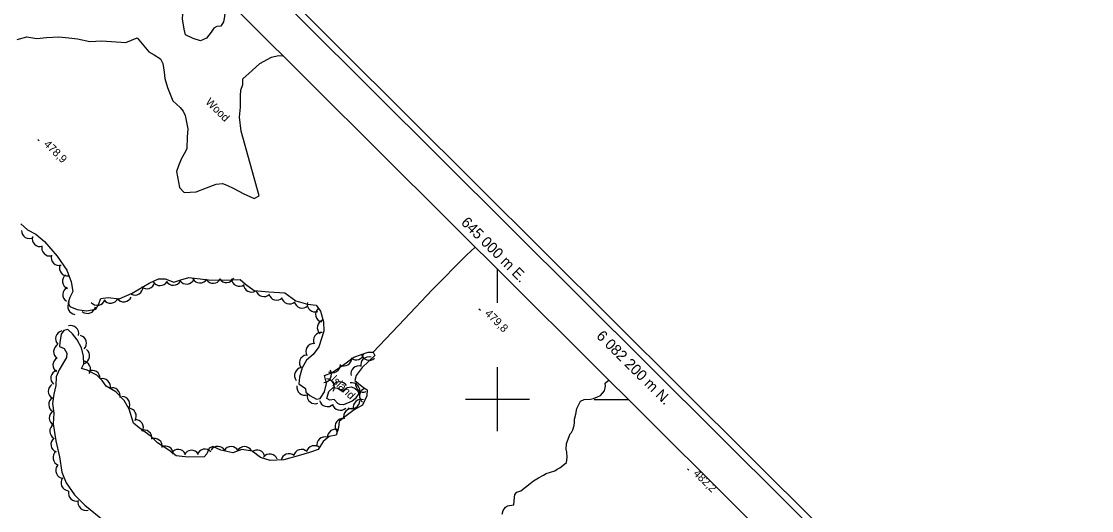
# Model space of a CAD drawing. Extents: x 642515 to 647219, y 6080136 to 6084356.
# Drawn here: x 644821.8 to 645222.7, y 6082158.4 to 6082341.5 of the extents above; entities that cross this region are included whole.
import ezdxf

# ---------------------------------------------------------------- set-up
doc = ezdxf.new("R2010")
doc.units = 0
for name, color, linetype in [('Level 1', 7, 'Continuous'), ('Level 2', 7, 'Continuous'), ('Level 3', 7, 'Continuous'), ('Level 4', 7, 'Continuous'), ('Level 44', 7, 'Continuous'), ('Level 60', 7, 'Continuous'), ('Level 61', 7, 'Continuous'), ('Level 8', 7, 'Continuous')]:
    doc.layers.add(name, color=color, linetype=linetype)

msp = doc.modelspace()

# ---------------------------------------------------------------- linework, layer by layer
at = {"layer": 'Level 1'}
for points in [[(644820.13, 6082334.71), (644823.82, 6082335.72), (644827.59, 6082335.11), (644831.11, 6082335.43), (644835.81, 6082335.68), (644839.57, 6082335.31), (644842.79, 6082335.04), (644847.43, 6082334.03), (644851.89, 6082334.27), (644860.86, 6082333.61), (644865.17, 6082335.31), (644869.48, 6082330.17), (644871.49, 6082328.98), (644873.84, 6082327.48)], [(644873.84, 6082327.48), (644874.73, 6082325.73), (644875.21, 6082322.51), (644875.49, 6082320.08), (644876.46, 6082316.71), (644878.48, 6082311.78), (644881.2, 6082309.32), (644882.4, 6082307.92), (644883.13, 6082306.33), (644884.18, 6082301.35), (644883.84, 6082298.24), (644883.71, 6082294), (644883.28, 6082292.84), (644881.63, 6082289.98), (644880.61, 6082287.49), (644879.9, 6082285.34), (644881, 6082279.38), (644882.71, 6082277.52), (644887.25, 6082277.76), (644891.07, 6082279.27), (644894.75, 6082280.61), (644897.17, 6082280.9), (644898.67, 6082280.17), (644901.32, 6082279.01), (644904.83, 6082277.09), (644908.98, 6082275.2), (644910.88, 6082276.28), (644904.05, 6082300.47), (644903.48, 6082305.64), (644903.79, 6082309.4), (644903.91, 6082313.64), (644903.97, 6082315.76), (644904.68, 6082317.91), (644904.75, 6082320.03), (644908.18, 6082323.15), (644911.14, 6082325.75), (644915.42, 6082328.09), (644918.15, 6082328.73), (644919.73, 6082328.64)], [(645018.38, 6082172.27), (645021.58, 6082173.26), (645022.52, 6082173.96), (645023.55, 6082174.42), (645024.65, 6082175.29), (645025.98, 6082176.42), (645026.3, 6082178.3), (645026.12, 6082180.32), (645025.91, 6082181.45), (645025.97, 6082183.56), (645027.35, 6082187.12), (645027.89, 6082187.72), (645028.42, 6082188.64), (645028.83, 6082190.29), (645028.94, 6082191.43), (645028.96, 6082192.65), (645029.44, 6082194.54), (645029.83, 6082196.67), (645031.24, 6082199.43), (645032.59, 6082200.07), (645034.95, 6082200.12), (645036.15, 6082200.43), (645037.58, 6082200.99), (645038.7, 6082201.54), (645040.24, 6082203.25), (645040.57, 6082204.97), (645040.51, 6082206.1), (645041.45, 6082206.96), (645041.94, 6082207.18)], [(645001.88, 6082157.1), (645002.22, 6082158.5), (645003.14, 6082159.69), (645003.93, 6082160.21), (645006.26, 6082160.58), (645006.54, 6082163.28), (645006.65, 6082164.42), (645007.43, 6082165.27), (645008.86, 6082165.84), (645012.39, 6082168.54), (645013.64, 6082169.58), (645015.53, 6082170.66), (645017.35, 6082171.65), (645018.38, 6082172.27)]]:
    msp.add_lwpolyline(points, dxfattribs=at)
at = {"layer": 'Level 2'}
msp.add_lwpolyline([(644897.23, 6082351), (644897.49, 6082348.13), (644898.11, 6082345.4), (644897.76, 6082342.62), (644897.49, 6082341.3), (644896.43, 6082339.78), (644894.98, 6082339.54), (644893.87, 6082338.99), (644892.8, 6082337.47), (644891.12, 6082335.27), (644888.9, 6082334.17), (644886.1, 6082335.16), (644883.28, 6082336.47), (644882.69, 6082338.55), (644882.18, 6082342.43), (644882.26, 6082344.22), (644878.57, 6082346.62)], dxfattribs=at)
at = {"layer": 'Level 3'}
for p, q in [((644827.89, 6082297.32), (644828.46, 6082296.76)), ((644993.17, 6082233.97), (644993.74, 6082233.41)), ((645071.29, 6082174.1), (645071.86, 6082173.54))]:
    msp.add_line(p, q, dxfattribs=at)
at = {"layer": 'Level 4'}
for points in [[(644821.58, 6082265.8), (644824.08, 6082263.54), (644827.12, 6082261.89), (644830.39, 6082259.1), (644835.11, 6082253.59), (644838.75, 6082248.43), (644840.46, 6082244.08), (644841.06, 6082240.41), (644839.95, 6082238.12), (644839.31, 6082236.36), (644839.96, 6082234.83), (644842.65, 6082233.66), (644846.12, 6082233.19), (644849.62, 6082233.78), (644850.59, 6082235.56), (644851.54, 6082237.84), (644854.31, 6082238.15), (644858.36, 6082237.63), (644863.25, 6082239.78), (644869.61, 6082243.58), (644873.1, 6082245.12), (644875.64, 6082245.18), (644878.83, 6082243.87), (644881.49, 6082244.75), (644884.44, 6082245.61), (644891.91, 6082244.73), (644896.96, 6082244.71), (644903.71, 6082244.95), (644905.73, 6082243.2), (644908.97, 6082240.83), (644914.41, 6082240.29), (644920.5, 6082239.96), (644924.6, 6082236.89), (644928.92, 6082235.72), (644932.18, 6082235.28), (644933.82, 6082233.02), (644934.89, 6082229.09), (644935.07, 6082225.56), (644933.17, 6082219.7), (644931.06, 6082216.83), (644928.59, 6082214.76), (644926.98, 6082211.84), (644925.97, 6082208.37), (644925.69, 6082205.89), (644928.2, 6082204.09), (644928.32, 6082202.74), (644929.89, 6082201.55), (644932.35, 6082200.12), (644933.73, 6082200.35)], [(644953.52, 6082217.74), (644965.25, 6082230.13), (644975.67, 6082241.06), (644988.52, 6082254), (644991.79, 6082257.02)], [(644852.03, 6082207.09), (644849.99, 6082209.16), (644846.45, 6082211.03), (644844.29, 6082211.57), (644845.14, 6082213.3), (644844.98, 6082216.26), (644844.29, 6082219.31), (644842.69, 6082222.31), (644840.93, 6082224.6), (644839.2, 6082226.23), (644837.67, 6082225.82), (644836.63, 6082224.41), (644836.22, 6082221.34), (644836.06, 6082219.85), (644837.73, 6082219.12), (644838.73, 6082217.36), (644838.65, 6082215.71), (644835.9, 6082211.16), (644834.77, 6082208.51), (644834.66, 6082205.26), (644833.89, 6082201.96), (644833.46, 6082198.45), (644833.89, 6082194.93), (644833.66, 6082190.85), (644834.65, 6082184.48), (644835.99, 6082178.51), (644836.91, 6082172.84), (644838.56, 6082168.86), (644841.66, 6082164.34), (644845.48, 6082160.51), (644852.89, 6082154.46)], [(644933.73, 6082200.35), (644935.32, 6082202.83), (644936.1, 6082205.95), (644935.33, 6082209), (644937.9, 6082209.96), (644942.1, 6082212.73), (644946.33, 6082215.79), (644951.64, 6082217.72), (644953.52, 6082217.74), (644954.2, 6082216.5), (644949.44, 6082211.97), (644947.17, 6082209.01), (644946.74, 6082207.14), (644949.48, 6082204.9), (644951.26, 6082203.68), (644951.18, 6082201.33), (644949.56, 6082197.95), (644946.5, 6082196.1), (644942.98, 6082193.57), (644940.82, 6082191.77), (644940.61, 6082189.54), (644939.69, 6082186.69), (644937.1, 6082186.14), (644934.86, 6082184.25), (644933.01, 6082181.32), (644929.74, 6082180.2), (644925.51, 6082178.94), (644920.13, 6082177.46), (644915.03, 6082177.15), (644911.36, 6082178.27), (644908.24, 6082180.69), (644904.31, 6082181.26), (644901.02, 6082180.02), (644896.45, 6082181.09), (644893.47, 6082182.45), (644892.15, 6082181.76), (644891.2, 6082179.66), (644890.27, 6082178.54), (644884.29, 6082178.46), (644879.76, 6082178.96), (644876.94, 6082181.03), (644872.78, 6082183.77), (644870.4, 6082186.15), (644865.88, 6082189.36), (644863.78, 6082191.1), (644862.19, 6082196.45), (644860.26, 6082199.59), (644857.13, 6082202.88), (644853.53, 6082205.03), (644852.03, 6082207.09)], [(644940.26, 6082198.52), (644938.99, 6082200.06), (644937.36, 6082199.81), (644936.23, 6082200.37), (644936.99, 6082202.96), (644938.6, 6082204.48), (644940.33, 6082204.24), (644941.9, 6082203.14), (644943.84, 6082204.52), (644945.39, 6082204.76), (644946.77, 6082204.14), (644947.67, 6082203.4), (644948.22, 6082202.28), (644946.85, 6082200.32), (644945.67, 6082199.43), (644942.42, 6082197.98), (644941.06, 6082198.12), (644940.26, 6082198.52)]]:
    msp.add_lwpolyline(points, dxfattribs=at)
at = {"layer": 'Level 44'}
for centre, start, end in [((644824.77, 6082263.26), 179.1199, 299.0978), ((644828.79, 6082260.23), 165.5966, 285.5745), ((644832.36, 6082256.73), 164.95, 284.9279), ((644835.89, 6082253.19), 164.95, 284.9279), ((644839.01, 6082249.23), 157.4267, 277.4046), ((644840.16, 6082244.31), 128.0985, 248.0764), ((644868.78, 6082244.42), 227.5856, 347.5635), ((644873.69, 6082245.62), 211.4736, 331.4515), ((644878.68, 6082245.75), 211.4736, 331.4515), ((644883.64, 6082246.21), 216.2174, 336.1953), ((644888.65, 6082246.64), 208.0571, 328.035), ((644893.62, 6082246.49), 213.1358, 333.1138), ((644898.62, 6082246.76), 213.1358, 333.1138), ((644903.44, 6082245.39), 185.06, 305.0379), ((644907.95, 6082243.2), 182.766, 302.744), ((644840.26, 6082239.27), 116.7131, 236.6911), ((644860.15, 6082239.56), 215.8674, 335.8454), ((644864.31, 6082242.1), 241.2708, 1.2488), ((644912.56, 6082241.52), 194.5901, 314.568), ((644917.39, 6082240.21), 195.351, 315.3289), ((644842.1, 6082234.82), 144.4243, 264.4022), ((644846.53, 6082235.21), 229.4916, 349.4696), ((644850.23, 6082238.24), 220.0217, 339.9997), ((644855.18, 6082239.05), 215.8674, 335.8454), ((644922.19, 6082238.78), 191.2815, 311.2594), ((644926.93, 6082237.22), 194.0894, 314.0673), ((644931.85, 6082235.78), 168.7912, 288.7691), ((644935, 6082231.9), 133.5572, 253.5351), ((644840.24, 6082224.68), 347.1631, 107.1411), ((644935.6, 6082226.9), 109.288, 229.2659), ((644837.57, 6082222.74), 103.7137, 223.6916), ((644843.17, 6082221.01), 316.2196, 76.1975), ((644934.17, 6082222.06), 83.743, 203.721), ((644836.83, 6082217.9), 117.1289, 237.1068), ((644844.33, 6082216.32), 291.7211, 51.699), ((644931.33, 6082217.99), 90.0898, 210.0678), ((644836.58, 6082212.91), 117.1289, 237.1068), ((644844.65, 6082211.35), 326.3635, 86.3414), ((644928.9, 6082213.68), 98.7959, 218.7739), ((644942.59, 6082215.58), 240.82, 0.7979), ((644947.11, 6082217.79), 230.8589, 350.8368), ((644951.89, 6082212.98), 72.4411, 192.419), ((644952.04, 6082217.7), 192.6782, 312.6561), ((644835.77, 6082207.94), 107.5557, 227.5336), ((644848.28, 6082207.92), 357.4167, 117.3947), ((644927.09, 6082209.02), 98.7959, 218.7739), ((644934.93, 6082209.37), 273.91, 33.8879), ((644938.3, 6082213.02), 240.82, 0.7979), ((644948.2, 6082209.61), 72.4411, 192.419), ((644852.12, 6082204.84), 347.1352, 107.1131), ((644936.02, 6082204.69), 329.1326, 89.1106), ((644941.06, 6082203.63), 31.5489, 151.5268), ((644945.58, 6082203.29), 342.1942, 102.1722), ((644949.96, 6082205.77), 170.1984, 290.1764), ((644834.81, 6082203.12), 122.2095, 242.1875), ((644855.78, 6082201.43), 347.1352, 107.1131), ((644927.96, 6082204.61), 170.497, 290.475), ((644951.47, 6082201.36), 111.9723, 231.9502), ((644835, 6082198.12), 122.2095, 242.1875), ((644859.38, 6082198.14), 328.7589, 88.7368), ((644931.82, 6082201.43), 170.497, 290.475), ((644936.41, 6082200.34), 194.0954, 314.0733), ((644941.21, 6082198.97), 194.0954, 314.0733), ((644945.52, 6082199.51), 241.6288, 1.6068), ((644949.07, 6082197.07), 72.3148, 192.2928), ((644835.19, 6082193.13), 122.2948, 242.2727), ((644861.79, 6082193.76), 328.7589, 88.7368), ((644945.5, 6082193.61), 77.3471, 197.3251), ((644835.39, 6082188.13), 122.2948, 242.2727), ((644864.46, 6082189.51), 333.9498, 93.9278), ((644942.29, 6082189.95), 98.3745, 218.3524), ((644867.67, 6082185.62), 351.1868, 111.1647), ((644939.45, 6082185.88), 64.434, 184.412), ((644835.82, 6082183.2), 129.4582, 249.4362), ((644871.56, 6082182.48), 351.1868, 111.1647), ((644875.67, 6082179.58), 358.6292, 118.6071), ((644895.38, 6082179.46), 29.2017, 149.1797), ((644900.38, 6082179.39), 29.2017, 149.1797), ((644905.38, 6082179.36), 30.0213, 149.9993), ((644931.5, 6082179.73), 46.2251, 166.2031), ((644935.42, 6082183), 71.8911, 191.869), ((644836.64, 6082178.27), 129.4582, 249.4362), ((644880.51, 6082178.3), 25.9521, 145.9301), ((644885.54, 6082178.02), 34.3793, 154.3573), ((644890.56, 6082178.43), 42.3395, 162.3174), ((644910.05, 6082178.11), 9.4471, 129.425), ((644914.86, 6082176.59), 21.6583, 141.6362), ((644921.98, 6082176.74), 49.0994, 169.0774), ((644926.7, 6082178.34), 46.2251, 166.2031), ((644837.63, 6082173.46), 143.2291, 263.207), ((644839.6, 6082168.86), 143.2291, 263.207), ((644842.35, 6082164.95), 166.2868, 286.2647), ((644845.96, 6082161.5), 166.2868, 286.2647)]:
    msp.add_arc(centre, 3, start, end, dxfattribs=at)
at = {"layer": 'Level 60'}
for p, q in [((645000.09, 6082236.21), (645000.09, 6082248.82)), ((645036.39, 6082200), (645049.08, 6082200))]:
    msp.add_line(p, q, dxfattribs=at)
for points in [[(643756.15, 6083509.1), (645893.11, 6081385.05), (644652.25, 6080135.58), (642514.75, 6082260.08)], [(642518.29, 6082260.09), (643756.16, 6083505.56), (645889.57, 6081385.04), (644651.74, 6080139.63)], [(643756.23, 6083485.06), (645517.55, 6081734.46), (644300.6, 6080509.08), (642538.79, 6082260.16)]]:
    msp.add_lwpolyline(points, close=True, dxfattribs=at)
at = {"layer": 'Level 61'}
for p, q in [((645000, 6082212.16), (645000, 6082188.16)), ((645012.16, 6082200), (644988.16, 6082200))]:
    msp.add_line(p, q, dxfattribs=at)

# ---------------------------------------------------------------- texts
at = {"layer": 'Level 3'}
for s, p in [('478,9', (644829.92, 6082295.27)), ('479,8', (644995.2, 6082231.92)), ('482,2', (645073.32, 6082172.05))]:
    msp.add_text(s, height=3, rotation=315.59, dxfattribs=at).set_placement(p)
at = {"layer": 'Level 44'}
msp.add_text('Wood', height=3, rotation=315.1749, dxfattribs=at).set_placement((644890.53, 6082311.1))
at = {"layer": 'Level 61'}
for s, p in [('645 000 m E.', (644986.23, 6082265.93)), ('6 082 200 m N.', (645036.91, 6082223.45))]:
    msp.add_text(s, height=4, rotation=315.175, dxfattribs=at).set_placement(p)
at = {"layer": 'Level 8'}
msp.add_text('Island', height=3, rotation=315.1749, dxfattribs=at).set_placement((644937.43, 6082207.36))

doc.saveas('drawing.dxf')
